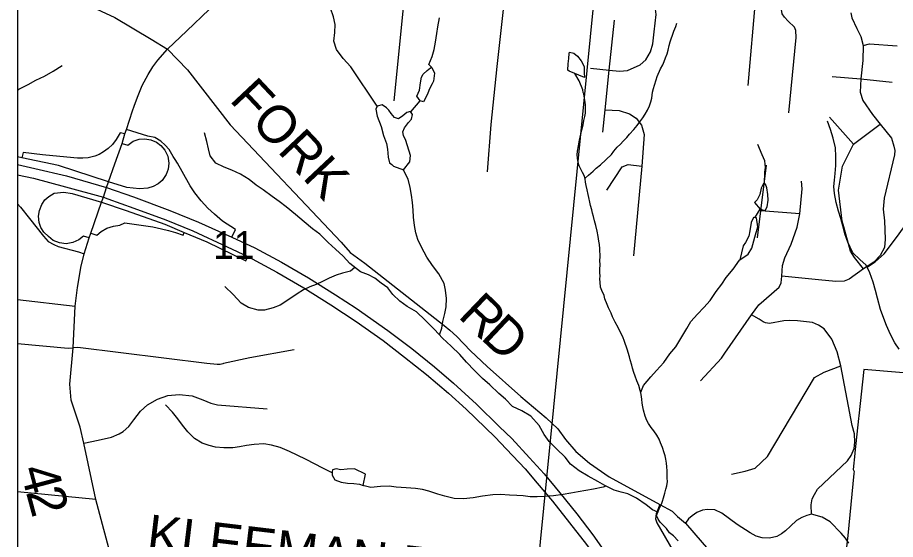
# Model space of a CAD drawing. Extents: x -8.2 to 38.5, y -0.1 to 21.9.
# Drawn here: x 2.163 to 3.486, y 19.487 to 20.274 of the extents above; entities that cross this region are included whole.
import ezdxf

# ---------------------------------------------------------------- set-up
doc = ezdxf.new("R2010")
doc.units = 0
for name, color, linetype in [('Default', 7, 'Continuous'), ('GM_X_Adjacent_County_Text', 7, 'Continuous'), ('GM_X_Airport_Location_Class_2', 7, 'Continuous'), ('GM_X_Airport_Location_Class_3', 7, 'Continuous'), ('GM_X_County_Road_Text', 7, 'Continuous'), ('GM_X_Interstate_Location', 7, 'Continuous'), ('GM_X_Minor_Lake', 7, 'Continuous'), ('GM_X_Minor_Lake_Text', 7, 'Continuous'), ('GM_X_Minor_River', 7, 'Continuous'), ('GM_X_Section', 7, 'Continuous'), ('GM_X_State_Location', 7, 'Continuous'), ('GM_X_Township_Text', 7, 'Continuous')]:
    doc.layers.add(name, color=color, linetype=linetype)

msp = doc.modelspace()

# ---------------------------------------------------------------- linework, layer by layer
at = {"layer": 'Default'}
for points in [[(3.7486, 17.3899), (3.8184, 18.0516), (3.8435, 18.2895), (3.8449, 18.303), (3.8472, 18.3279), (3.8854, 18.7517), (3.9289, 19.2353), (3.9436, 19.3979), (3.9961, 19.9817), (4.0302, 20.3597), (4.0404, 20.4649), (4.0467, 20.5533), (4.0665, 20.7635), (4.0666, 20.7645), (2.1634, 20.7645), (2.1634, 15.4317)], [(3.5456, 19.7345), (3.4381, 19.7434), (3.4307, 19.6733), (3.4303, 19.6696), (3.4245, 19.618), (3.4244, 19.6168), (3.4221, 19.5928), (3.4233, 19.5895), (3.423, 19.5868), (3.4138, 19.493), (3.4055, 19.4191)]]:
    msp.add_lwpolyline(points, dxfattribs=at)
msp.add_lwpolyline([(2.1634, 20.4819), (2.1634, 19.4712), (2.9408, 19.3823), (3.0413, 20.3975)], close=True, dxfattribs=at)
at = {"layer": 'GM_X_Adjacent_County_Text'}
msp.add_lwpolyline([(3.0413, 20.3975), (4.0367, 20.2914), (3.9431, 19.2991), (2.9408, 19.3823)], close=True, dxfattribs=at)
at = {"layer": 'GM_X_Airport_Location_Class_2'}
for p, q in [((3.2757, 20.3104), (3.2633, 20.1713)), ((3.4226, 20.0829), (3.3864, 20.1238)), ((3.3419, 19.9782), (3.283, 19.9824)), ((2.1634, 19.849), (2.25, 19.8388)), ((2.2811, 19.5474), (2.1634, 19.5592))]:
    msp.add_line(p, q, dxfattribs=at)
for points in [[(2.7563, 20.3938), (2.7551, 20.3718), (2.7545, 20.363), (2.7524, 20.3494), (2.749, 20.3391), (2.7302, 20.1485)], [(2.9036, 20.3635), (2.8852, 20.2003), (2.8761, 20.1127), (2.8707, 20.0414)], [(3.0263, 20.1974), (3.0546, 20.1948), (3.0702, 20.1932), (3.0822, 20.1942), (3.1012, 20.2028), (3.1098, 20.2103), (3.1169, 20.2221), (3.1202, 20.2344), (3.1224, 20.2523), (3.1252, 20.2786), (3.1245, 20.2864), (3.1158, 20.3093), (3.1155, 20.3179), (3.1167, 20.328)], [(3.325, 20.1305), (3.3364, 20.2437), (3.3356, 20.2543), (3.3335, 20.2592), (3.3239, 20.2683), (3.3186, 20.2745), (3.315, 20.2795), (3.314, 20.2859), (3.3145, 20.296), (3.316, 20.3063), (3.3169, 20.3159)], [(3.4186, 20.2812), (3.4202, 20.2735), (3.4276, 20.2575), (3.4334, 20.2455), (3.4372, 20.2317), (3.4367, 20.2092), (3.4338, 20.1814), (3.4324, 20.1613), (3.4367, 20.1489), (3.4511, 20.128), (3.4628, 20.1134), (3.4797, 20.0922), (3.4834, 20.0803), (3.4846, 20.0736), (3.4842, 20.0668), (3.4688, 20.0015), (3.4674, 19.9851), (3.4691, 19.9673), (3.4704, 19.9399), (3.469, 19.9274), (3.4627, 19.915), (3.4531, 19.9051), (3.4377, 19.8949), (3.4161, 19.8795), (3.4083, 19.8767), (3.396, 19.8762), (3.3697, 19.8786), (3.3148, 19.8843)], [(3.0448, 20.1012), (3.0483, 20.1349), (3.0546, 20.1948), (3.0625, 20.2701)], [(3.4372, 20.2317), (3.4468, 20.2344), (3.4883, 20.2315)], [(3.3903, 20.1849), (3.4338, 20.1814), (3.4809, 20.1763)], [(3.0483, 20.1349), (3.0697, 20.1336), (3.0852, 20.129), (3.0951, 20.1224), (3.103, 20.1115), (3.1074, 20.0975), (3.1035, 20.0497), (3.0914, 19.9146)], [(3.4377, 19.8949), (3.4238, 19.9122), (3.4178, 19.922), (3.4079, 19.9586), (3.4055, 19.9672), (3.3999, 20.0139), (3.4059, 20.05), (3.4226, 20.0829), (3.4628, 20.1134)], [(3.0508, 20.0139), (3.0742, 20.049), (3.0832, 20.0522), (3.1035, 20.0497)], [(3.278, 19.9417), (3.283, 19.9824), (3.2916, 20.0516)], [(3.1919, 19.7265), (3.2237, 19.7605), (3.2288, 19.768), (3.269, 19.8256), (3.2799, 19.8409), (3.3105, 19.8676), (3.3137, 19.8739), (3.3148, 19.8843), (3.3157, 19.9003), (3.3192, 19.9115), (3.3285, 19.9321), (3.3377, 19.9579), (3.3419, 19.9782), (3.3452, 20.0158), (3.3442, 20.0275)], [(3.3593, 19.5251), (3.3589, 19.5393), (3.3605, 19.5482), (3.3637, 19.5551), (3.3684, 19.563), (3.3863, 19.5802), (3.4134, 19.6059), (3.4188, 19.6136), (3.4234, 19.6242), (3.4247, 19.6338), (3.424, 19.6465), (3.4204, 19.6592), (3.4034, 19.7488), (3.398, 19.7698), (3.3897, 19.7892), (3.3786, 19.8049), (3.3697, 19.8104), (3.3606, 19.814), (3.3383, 19.8169), (3.3263, 19.8172), (3.3178, 19.8166), (3.2961, 19.8127), (3.2901, 19.8136), (3.2864, 19.8154), (3.2806, 19.8193), (3.269, 19.8256)], [(2.4736, 19.7522), (2.4726, 19.752), (2.4688, 19.7511), (2.464, 19.7509), (2.4483, 19.7522), (2.254, 19.7766), (2.2471, 19.7759)], [(2.5802, 19.7732), (2.5133, 19.761), (2.4736, 19.7522)], [(3.2389, 19.5857), (3.2592, 19.5902), (3.2742, 19.5949), (3.2929, 19.6122), (3.3637, 19.7312), (3.3785, 19.7396), (3.4034, 19.7488)], [(2.263, 19.6324), (2.2846, 19.6368), (2.305, 19.6414), (2.3166, 19.6462), (2.3223, 19.6499), (2.3312, 19.6576), (2.3384, 19.6676), (2.3485, 19.6808), (2.3593, 19.6903), (2.3742, 19.6989), (2.3898, 19.704), (2.4069, 19.7058), (2.4266, 19.7035), (2.4423, 19.6977), (2.4544, 19.6927), (2.4646, 19.69), (2.5395, 19.684)], [(3.4156, 19.4817), (3.4107, 19.4891), (3.4039, 19.4969), (3.3872, 19.5136), (3.3752, 19.5206), (3.3593, 19.5251), (3.3524, 19.5233), (3.3447, 19.5205), (3.3367, 19.5156), (3.3274, 19.5073), (3.3201, 19.5001), (3.3141, 19.4956), (3.3071, 19.4918), (3.2962, 19.4892), (3.2852, 19.4895), (3.2759, 19.4923), (3.2669, 19.4974), (3.2471, 19.5099), (3.2243, 19.527), (3.2135, 19.5316), (3.2027, 19.5323), (3.1949, 19.5311), (3.1868, 19.5276), (3.1796, 19.5229), (3.1741, 19.5184), (3.1693, 19.5119)]]:
    msp.add_lwpolyline(points, dxfattribs=at)
at = {"layer": 'GM_X_Airport_Location_Class_3'}
for points in [[(2.1634, 20.0368), (2.1872, 20.0316), (2.2356, 20.0186), (2.2926, 20.0031), (2.2992, 20.0007)], [(2.2992, 20.0007), (2.3385, 19.9868), (2.3865, 19.9688), (2.4276, 19.9522), (2.4793, 19.9285), (2.5102, 19.9135)], [(2.5102, 19.9135), (2.5541, 19.8901), (2.5947, 19.8666), (2.6355, 19.8407), (2.6734, 19.8157), (2.7142, 19.787), (2.7462, 19.7622), (2.7794, 19.7357), (2.8125, 19.7078), (2.839, 19.6837), (2.8824, 19.6418), (2.9, 19.6234), (2.9279, 19.5938), (2.9461, 19.5721), (2.9693, 19.5449), (2.995, 19.5122), (3.0202, 19.4795), (3.0406, 19.4508), (3.0667, 19.413), (3.3668, 18.9788), (3.4094, 18.917)]]:
    msp.add_lwpolyline(points, dxfattribs=at)
at = {"layer": 'GM_X_Interstate_Location'}
for points in [[(2.3248, 20.0984), (2.3177, 20.1004), (2.3121, 20.0901), (2.3066, 20.0827), (2.2999, 20.0763), (2.293, 20.0714), (2.2861, 20.0677), (2.2796, 20.0651), (2.2697, 20.0627), (2.2615, 20.0618), (2.2538, 20.0619), (2.2479, 20.0627), (2.2012, 20.0669), (2.1718, 20.0706), (2.1698, 20.0627)], [(2.4009, 20.06), (2.398, 20.0647), (2.3915, 20.0748), (2.3859, 20.0816), (2.3793, 20.0876), (2.3701, 20.093), (2.3594, 20.0951), (2.3356, 20.1029), (2.3277, 20.1054)], [(2.3207, 20.0842), (2.3294, 20.0817), (2.3377, 20.0874), (2.3465, 20.0906), (2.3552, 20.0913), (2.3643, 20.0898), (2.3729, 20.086), (2.3793, 20.0812), (2.3853, 20.074), (2.3895, 20.0651), (2.3912, 20.0546), (2.3903, 20.0455), (2.3873, 20.0372), (2.3813, 20.0285), (2.3751, 20.0231), (2.3677, 20.0191), (2.3595, 20.0169), (2.3469, 20.0158), (2.3279, 20.0176), (2.3006, 20.0265), (2.2253, 20.0508), (2.1698, 20.0627), (2.1634, 20.0639)], [(2.4862, 19.943), (2.4916, 19.9542), (2.4723, 19.9671), (2.4598, 19.9773), (2.45, 19.9866), (2.4399, 19.9977), (2.4306, 20.0096), (2.4234, 20.0205), (2.4111, 20.0419), (2.4044, 20.0543), (2.4009, 20.06)], [(2.2713, 19.9417), (2.2627, 19.9445), (2.2557, 19.9391), (2.2468, 19.9347), (2.2364, 19.933), (2.2266, 19.9343), (2.217, 19.9381), (2.2098, 19.9437), (2.2029, 19.9506), (2.1986, 19.9576), (2.1961, 19.9649), (2.195, 19.9744), (2.1962, 19.9833), (2.1998, 19.9923), (2.2047, 19.9992), (2.2104, 20.0044), (2.2186, 20.009), (2.2332, 20.0105), (2.2458, 20.0086), (2.2899, 19.9955), (2.3271, 19.9829), (2.3851, 19.9624), (2.4142, 19.95), (2.4483, 19.9356), (2.5074, 19.9072), (2.5102, 19.9135)], [(2.1634, 19.9932), (2.1677, 19.988), (2.1814, 19.9708)], [(2.1814, 19.9708), (2.2026, 19.9442), (2.2097, 19.9363), (2.2181, 19.9316), (2.2247, 19.9289), (2.2551, 19.9207), (2.2639, 19.918)], [(2.2738, 19.9491), (2.2829, 19.9458), (2.2891, 19.9515), (2.2981, 19.9564), (2.3079, 19.9595), (2.3174, 19.9609), (2.3251, 19.9643), (2.3671, 19.9583), (2.3802, 19.9556), (2.3906, 19.953), (2.4014, 19.9499), (2.413, 19.946), (2.4142, 19.95)]]:
    msp.add_lwpolyline(points, dxfattribs=at)
at = {"layer": 'GM_X_Minor_Lake_Text'}
msp.add_line((3.0173, 20.1836), (2.9944, 20.1933), dxfattribs=at)
for points in [[(2.9944, 20.1933), (2.9921, 20.1946), (2.993, 20.204), (2.994, 20.2124), (2.9945, 20.2196), (2.9949, 20.2218), (3.0014, 20.2202), (3.0066, 20.2155), (3.0121, 20.2085), (3.0147, 20.2043), (3.0169, 20.1997), (3.0171, 20.191), (3.0173, 20.1836)], [(2.7696, 20.1482), (2.7648, 20.1552), (2.7689, 20.1646), (2.7702, 20.1756), (2.7719, 20.1839), (2.7743, 20.1888), (2.7805, 20.1939), (2.7852, 20.198), (2.7875, 20.1987), (2.7914, 20.1903), (2.79, 20.1782), (2.7881, 20.174), (2.7841, 20.1665), (2.7813, 20.1597), (2.7789, 20.1545), (2.7749, 20.147)], [(2.7449, 20.0442), (2.7543, 20.0563), (2.7553, 20.0662), (2.7482, 20.0887), (2.7449, 20.096), (2.7439, 20.1017), (2.7463, 20.1078), (2.7522, 20.1156), (2.7569, 20.1208), (2.7582, 20.128), (2.7552, 20.1322), (2.7495, 20.1308), (2.7437, 20.1257), (2.7371, 20.1212), (2.7311, 20.1233), (2.7263, 20.1291), (2.7226, 20.1345), (2.7189, 20.1376), (2.7125, 20.1423), (2.7049, 20.1402), (2.7029, 20.1357), (2.7053, 20.1254), (2.7111, 20.1097), (2.7146, 20.0959), (2.7192, 20.0841), (2.7206, 20.0753), (2.7214, 20.0635), (2.7235, 20.0551), (2.7269, 20.0524), (2.7299, 20.05)], [(2.7749, 20.147), (2.7696, 20.1482)], [(2.7299, 20.05), (2.7449, 20.0442)], [(3.2822, 19.985), (3.2897, 19.9833), (3.2925, 19.9886), (3.2939, 19.9988), (3.2933, 20.0071), (3.292, 20.017), (3.2902, 20.0228), (3.2868, 20.0236), (3.2833, 20.0169), (3.2815, 20.0074), (3.2775, 19.9991), (3.2733, 19.9951), (3.2822, 19.985)], [(3.2511, 19.9088), (3.264, 19.917), (3.2695, 19.9264), (3.2737, 19.943), (3.2786, 19.9585), (3.2762, 19.9718), (3.272, 19.9723), (3.2684, 19.9652), (3.2666, 19.9523), (3.2649, 19.9444), (3.2598, 19.9346), (3.2563, 19.9297), (3.2511, 19.9088)], [(2.6842, 19.5687), (2.6874, 19.5855), (2.6708, 19.5938), (2.6598, 19.5933), (2.6503, 19.592), (2.6431, 19.5937), (2.6378, 19.5923), (2.6373, 19.5889), (2.6372, 19.5839), (2.6412, 19.577), (2.6506, 19.5738), (2.6605, 19.572), (2.67, 19.5714), (2.6783, 19.5705)], [(2.6783, 19.5705), (2.6841, 19.5687)]]:
    msp.add_lwpolyline(points, dxfattribs=at)
at = {"layer": 'GM_X_Minor_River'}
for points in [[(2.7049, 20.1402), (2.6655, 20.1994), (2.6536, 20.2122), (2.6437, 20.2258), (2.6398, 20.2384), (2.6413, 20.2513), (2.6416, 20.2635), (2.6392, 20.2749), (2.6346, 20.2883)], [(2.7873, 20.1987), (2.783, 20.203), (2.7878, 20.2154), (2.7908, 20.226), (2.7929, 20.237), (2.7951, 20.2498), (2.7965, 20.2601), (2.7987, 20.2737)], [(3.0188, 20.0324), (3.0235, 20.0365), (3.0305, 20.0424), (3.0351, 20.0468), (3.0414, 20.0519), (3.0578, 20.0675), (3.0617, 20.0727), (3.0664, 20.0783), (3.0715, 20.0831), (3.0758, 20.0875), (3.0809, 20.0931), (3.0852, 20.0983), (3.0915, 20.1054), (3.0966, 20.1113), (3.1005, 20.1165), (3.1053, 20.1229), (3.1088, 20.1285), (3.112, 20.1341), (3.1153, 20.1409), (3.1173, 20.1469), (3.1186, 20.1526), (3.1191, 20.1571), (3.12, 20.1617), (3.1213, 20.167), (3.1229, 20.1722), (3.1254, 20.1798), (3.1267, 20.1851), (3.1316, 20.1964), (3.1352, 20.2027), (3.1372, 20.2076), (3.1396, 20.2133), (3.1417, 20.2193), (3.1434, 20.2246), (3.1451, 20.2318), (3.1464, 20.2371), (3.148, 20.2416), (3.1497, 20.2472), (3.1521, 20.2533), (3.155, 20.2604), (3.1566, 20.2657)], [(2.1634, 20.1645), (2.1654, 20.166), (2.1792, 20.1729), (2.1911, 20.1794), (2.2042, 20.1855), (2.2169, 20.1932), (2.2308, 20.2016)], [(3.0154, 20.1612), (3.0146, 20.165), (3.0094, 20.1787), (3.0028, 20.1897)], [(3.0402, 19.9252), (3.0397, 19.9317), (3.039, 19.9367), (3.0381, 19.9439), (3.0364, 19.952), (3.0343, 19.9604), (3.0326, 19.9677), (3.0309, 19.9742), (3.0295, 19.9792), (3.0285, 19.9842), (3.0264, 19.9907), (3.0254, 19.9957), (3.0241, 20.0026), (3.0231, 20.0072), (3.0213, 20.0141), (3.02, 20.0206), (3.019, 20.0259), (3.0184, 20.0309), (3.0166, 20.0359), (3.0144, 20.0405), (3.0094, 20.0506), (3.0076, 20.0556), (3.0067, 20.0621), (3.0064, 20.067), (3.0069, 20.0723), (3.0083, 20.0807), (3.01, 20.089), (3.0131, 20.1049), (3.0152, 20.1124), (3.0165, 20.1189), (3.0178, 20.1249), (3.0187, 20.1299), (3.0189, 20.1359), (3.0187, 20.142), (3.0184, 20.1466), (3.0174, 20.1523), (3.0161, 20.1589), (3.0154, 20.1612)], [(2.7556, 20.1317), (2.7696, 20.1482)], [(3.4912, 19.774), (3.485, 19.7836), (3.4785, 19.796), (3.472, 19.8098), (3.4666, 19.8244), (3.463, 19.834), (3.4589, 19.8508), (3.4557, 19.8623), (3.4522, 19.8749), (3.4473, 19.8891), (3.4418, 19.9007), (3.4322, 19.9093), (3.4214, 19.9194), (3.4138, 19.9352), (3.4095, 19.9478), (3.4064, 19.9601), (3.4033, 19.9708), (3.4001, 19.9823), (3.3966, 19.9953), (3.3939, 20.0087), (3.393, 20.0193), (3.394, 20.0288), (3.395, 20.039), (3.3961, 20.0508), (3.396, 20.0645), (3.3952, 20.0774), (3.3921, 20.092), (3.3879, 20.1054), (3.3832, 20.1176)], [(3.1277, 19.5284), (3.1198, 19.5317), (3.1101, 19.5396), (3.0959, 19.5494), (3.0828, 19.5558), (3.0726, 19.5587), (3.062, 19.5613), (3.0478, 19.5685), (3.0373, 19.5748), (3.023, 19.5828), (3.0095, 19.5907), (2.9961, 19.6009), (2.988, 19.611), (2.975, 19.6239), (2.9639, 19.6348), (2.9565, 19.6456), (2.9489, 19.6591), (2.9367, 19.6731), (2.9228, 19.681), (2.9089, 19.6874), (2.8985, 19.6987), (2.8881, 19.7073), (2.8747, 19.7202), (2.8639, 19.7296), (2.8517, 19.7421), (2.8398, 19.7545), (2.8298, 19.7658), (2.8165, 19.7787), (2.8035, 19.7908), (2.7916, 19.8036), (2.7775, 19.818), (2.7641, 19.8301), (2.7503, 19.8384), (2.7391, 19.8463), (2.7287, 19.8565), (2.7209, 19.8665), (2.7112, 19.8736), (2.7015, 19.8811), (2.6918, 19.8863), (2.6797, 19.8904), (2.6637, 19.9033), (2.6537, 19.9142), (2.6425, 19.9247), (2.631, 19.9349), (2.6188, 19.9473), (2.6076, 19.9556), (2.5953, 19.9662), (2.5822, 19.9771), (2.5681, 19.9885), (2.5572, 19.9964), (2.5468, 20.0042), (2.5333, 20.0141), (2.5229, 20.0215), (2.5121, 20.0298), (2.4993, 20.0377), (2.4862, 20.0437), (2.4745, 20.0486), (2.4621, 20.0546), (2.4533, 20.0654), (2.4512, 20.0761), (2.4485, 20.0872), (2.445, 20.1002)], [(3.2886, 20.0232), (3.2891, 20.041), (3.29, 20.0478), (3.2891, 20.0577), (3.2851, 20.0669), (3.2786, 20.0826)], [(2.7991, 19.7955), (2.8027, 19.8056), (2.8041, 19.8155), (2.807, 19.8279), (2.8088, 19.8378), (2.8095, 19.8503), (2.8082, 19.8629), (2.8058, 19.8732), (2.7978, 19.8875), (2.7886, 19.9002), (2.7798, 19.9126), (2.7718, 19.9276), (2.7664, 19.9392), (2.7632, 19.9495), (2.7612, 19.9606), (2.76, 19.9728), (2.7595, 19.9838), (2.7582, 19.9953), (2.757, 20.0063), (2.755, 20.0178), (2.7515, 20.0304), (2.7464, 20.0408), (2.7449, 20.0442)], [(3.4432, 19.8977), (3.4449, 19.8994), (3.4553, 19.9057), (3.4689, 19.9179), (3.4814, 19.9343), (3.4912, 19.9477), (3.5027, 19.9642), (3.5125, 19.9784), (3.5212, 19.9915), (3.5291, 20.0035), (3.5373, 20.0162), (3.5424, 20.0244)], [(3.2737, 19.9721), (3.2822, 19.985)], [(3.1585, 19.4853), (3.1514, 19.4927), (3.1455, 19.4974), (3.1407, 19.5037), (3.1363, 19.508), (3.1311, 19.5131), (3.1282, 19.5177), (3.126, 19.5231), (3.1281, 19.5295), (3.1305, 19.5348), (3.1333, 19.5404), (3.135, 19.5449), (3.1363, 19.5499), (3.1383, 19.557), (3.14, 19.5631), (3.1413, 19.568), (3.1422, 19.5748), (3.142, 19.5798), (3.1421, 19.5851), (3.1419, 19.5904), (3.1413, 19.5969), (3.1407, 19.6023), (3.1397, 19.608), (3.1387, 19.613), (3.1373, 19.6176), (3.1349, 19.626), (3.132, 19.633), (3.1299, 19.6384), (3.1263, 19.6445), (3.1219, 19.6511), (3.1178, 19.6562), (3.1138, 19.662), (3.1113, 19.6667), (3.1088, 19.6732), (3.1063, 19.682), (3.105, 19.687), (3.1043, 19.6924), (3.1037, 19.6985), (3.1028, 19.7057), (3.1014, 19.7116), (3.099, 19.7192), (3.0961, 19.7265), (3.0937, 19.7334), (3.0915, 19.7388), (3.0898, 19.7453), (3.0888, 19.7499), (3.0863, 19.758), (3.0853, 19.7626), (3.0818, 19.7741), (3.0776, 19.7856), (3.0751, 19.7925), (3.07, 19.8022), (3.0679, 19.8068), (3.0635, 19.8149), (3.0595, 19.8227), (3.0574, 19.8281), (3.0535, 19.8365), (3.0513, 19.8415), (3.0481, 19.85), (3.0471, 19.855), (3.0435, 19.8623), (3.0417, 19.8673), (3.0412, 19.875), (3.0405, 19.8795), (3.0407, 19.8845), (3.0404, 19.8891), (3.0406, 19.8948), (3.0407, 19.9012), (3.0405, 19.9077), (3.0407, 19.913), (3.0402, 19.9252)], [(3.1029, 19.7052), (3.1021, 19.7093), (3.1061, 19.7195), (3.1171, 19.7322), (3.1257, 19.7418), (3.137, 19.7541), (3.146, 19.7668), (3.155, 19.7776), (3.1657, 19.7952), (3.1716, 19.805), (3.1776, 19.8155), (3.1874, 19.8266), (3.1971, 19.8367), (3.2065, 19.8475), (3.2155, 19.8609), (3.2242, 19.8721), (3.2305, 19.8819), (3.2411, 19.8945), (3.2509, 19.9084), (3.2511, 19.9088)], [(2.6715, 19.8969), (2.6649, 19.8915), (2.6527, 19.8887), (2.6431, 19.8855), (2.6327, 19.8812), (2.6227, 19.8758), (2.6131, 19.8715), (2.6035, 19.8679), (2.5939, 19.8636), (2.5843, 19.8573), (2.5688, 19.8471), (2.5588, 19.8405), (2.5484, 19.8362), (2.5354, 19.833), (2.5259, 19.8329), (2.5112, 19.8367), (2.5, 19.8434), (2.4881, 19.8563), (2.4755, 19.8687)], [(2.6373, 19.5876), (2.6232, 19.5948), (2.6108, 19.6012), (2.598, 19.6076), (2.5845, 19.6144), (2.5729, 19.62), (2.559, 19.6257), (2.5461, 19.6294), (2.5344, 19.6312), (2.5199, 19.6304), (2.5081, 19.6288), (2.4978, 19.6268), (2.4875, 19.6255), (2.4742, 19.6251), (2.4617, 19.6261), (2.4519, 19.6286), (2.4413, 19.6323), (2.4301, 19.6394), (2.4201, 19.6492), (2.4119, 19.6593), (2.4046, 19.669), (2.3968, 19.679), (2.3861, 19.6903)], [(3.0497, 19.5675), (3.0454, 19.5662), (3.0309, 19.5628), (3.0195, 19.5612), (3.008, 19.5588), (2.9969, 19.5568), (2.9851, 19.5552), (2.9706, 19.5532), (2.9577, 19.552), (2.9463, 19.5512), (2.9356, 19.5514), (2.925, 19.5528), (2.9152, 19.5535), (2.9045, 19.5541), (2.8909, 19.5548), (2.8791, 19.5543), (2.8635, 19.5524), (2.8497, 19.5501), (2.8352, 19.5486), (2.8208, 19.5489), (2.8072, 19.5523), (2.7963, 19.5556), (2.7831, 19.5601), (2.7733, 19.5626), (2.763, 19.564), (2.7486, 19.5651), (2.7338, 19.5662), (2.7232, 19.5673), (2.7103, 19.5668), (2.6954, 19.5657), (2.6856, 19.5682), (2.6841, 19.5687)]]:
    msp.add_lwpolyline(points, dxfattribs=at)
at = {"layer": 'GM_X_Section'}
msp.add_lwpolyline([(8.9634, 15.3136), (8.9634, 20.7645), (2.1634, 20.7645), (2.1634, 13.9645)], dxfattribs=at)
at = {"layer": 'GM_X_State_Location'}
for points in [[(2.1634, 20.0524), (2.1895, 20.0466), (2.2371, 20.0351), (2.2976, 20.0178), (2.3382, 20.0037), (2.393, 19.9829), (2.4358, 19.9653), (2.4862, 19.943), (2.5208, 19.9267), (2.5611, 19.9052), (2.6017, 19.8817), (2.6425, 19.8559), (2.6735, 19.8359), (2.7212, 19.8021), (2.7573, 19.7749), (2.7915, 19.7475), (2.82, 19.7229), (2.8549, 19.6911), (2.8894, 19.6569), (2.9078, 19.6396), (2.9347, 19.6102), (2.9565, 19.5859), (2.9804, 19.5576), (3.0056, 19.526), (3.0299, 19.4944), (3.0501, 19.4657)], [(2.1634, 20.0368), (2.1872, 20.0316), (2.2356, 20.0186), (2.2926, 20.0031), (2.2992, 20.0007)], [(2.2992, 20.0007), (2.3385, 19.9868), (2.3865, 19.9688), (2.4276, 19.9522), (2.4793, 19.9285), (2.5102, 19.9135)], [(2.5102, 19.9135), (2.5541, 19.8901), (2.5947, 19.8666), (2.6355, 19.8407), (2.6734, 19.8157), (2.7142, 19.787), (2.7462, 19.7622), (2.7794, 19.7357), (2.8125, 19.7078), (2.839, 19.6837), (2.8824, 19.6418), (2.9, 19.6234), (2.9279, 19.5938), (2.9461, 19.5721), (2.9693, 19.5449), (2.995, 19.5122), (3.0202, 19.4795), (3.0406, 19.4508), (3.0667, 19.413), (3.3668, 18.9788), (3.4094, 18.917)]]:
    msp.add_lwpolyline(points, dxfattribs=at)
at = {"layer": 'GM_X_Township_Text'}
for points in [[(2.3391, 20.1402), (2.3439, 20.1541), (2.351, 20.1716), (2.3599, 20.188), (2.3671, 20.1994), (2.3749, 20.2098), (2.3893, 20.2262), (2.4183, 20.254), (2.4522, 20.2863), (2.4644, 20.2991), (2.4765, 20.3163), (2.4879, 20.3334), (2.513, 20.3716), (2.528, 20.3945), (2.5359, 20.4072)], [(2.1634, 20.3061), (2.2462, 20.3004), (2.2545, 20.299), (2.262, 20.2961), (2.3101, 20.2742), (2.3648, 20.2415), (2.3893, 20.2262)], [(2.3893, 20.2262), (2.4193, 20.1951), (2.4838, 20.112), (2.6506, 19.9355), (2.6646, 19.9196), (2.6866, 19.9035), (2.806, 19.8097), (2.8146, 19.8027), (2.825, 19.7929), (2.8457, 19.7715), (2.8709, 19.7481), (2.9214, 19.7028), (2.9597, 19.6707), (2.9771, 19.654), (2.9885, 19.6381), (3.0043, 19.6199), (3.0251, 19.6023), (3.0546, 19.5814), (3.1307, 19.5397), (3.1493, 19.5297), (3.1576, 19.522), (3.1693, 19.5119), (3.2512, 19.417)], [(2.3277, 20.1054), (2.3367, 20.1333), (2.3391, 20.1402)], [(2.3099, 20.0533), (2.3207, 20.0842), (2.3248, 20.0984), (2.3277, 20.1054)], [(2.2639, 19.918), (2.2713, 19.9417), (2.2738, 19.9491), (2.2899, 19.9955), (2.2926, 20.0031), (2.2976, 20.0178), (2.3006, 20.0265), (2.3099, 20.0533)], [(2.2565, 19.8844), (2.2586, 19.8971), (2.2639, 19.918)], [(2.25, 19.8388), (2.2537, 19.8672), (2.2565, 19.8844)], [(2.3069, 19.4514), (2.2811, 19.5474), (2.263, 19.6324), (2.2579, 19.6566), (2.2439, 19.6972), (2.2423, 19.7212), (2.2471, 19.7759), (2.25, 19.8388)], [(2.1634, 19.7824), (2.2397, 19.7754), (2.2471, 19.7759)], [(3.1307, 19.5397), (3.1255, 19.526), (3.1244, 19.5184), (3.1262, 19.5124), (3.1747, 19.4286), (3.209, 19.3678), (3.21, 19.3604), (3.2067, 19.3575), (3.2042, 19.3566), (3.145, 19.3637)]]:
    msp.add_lwpolyline(points, dxfattribs=at)

# ---------------------------------------------------------------- texts
at = {"layer": 'GM_X_County_Road_Text'}
msp.add_text('11', height=0.04186, rotation=0, dxfattribs=at).set_placement((2.458, 19.9102))
at = {"layer": 'GM_X_Minor_Lake'}
for s, height, rotation, p in [('FORK', 0.05682, 313.2792, (2.4812, 20.1489)), ('R', 0.0568, 316.2137, (2.8253, 19.8231)), ('D', 0.0568, 316.7754, (2.8594, 19.7904)), ('4', 0.0568, 284.8735, (2.1668, 19.5927)), ('2', 0.0568, 285.0992, (2.1758, 19.5587)), ('KLEEMAN RD', 0.05682, 353.1486, (2.3562, 19.4688))]:
    msp.add_text(s, height=height, rotation=rotation, dxfattribs=at).set_placement(p)

doc.saveas('drawing.dxf')
